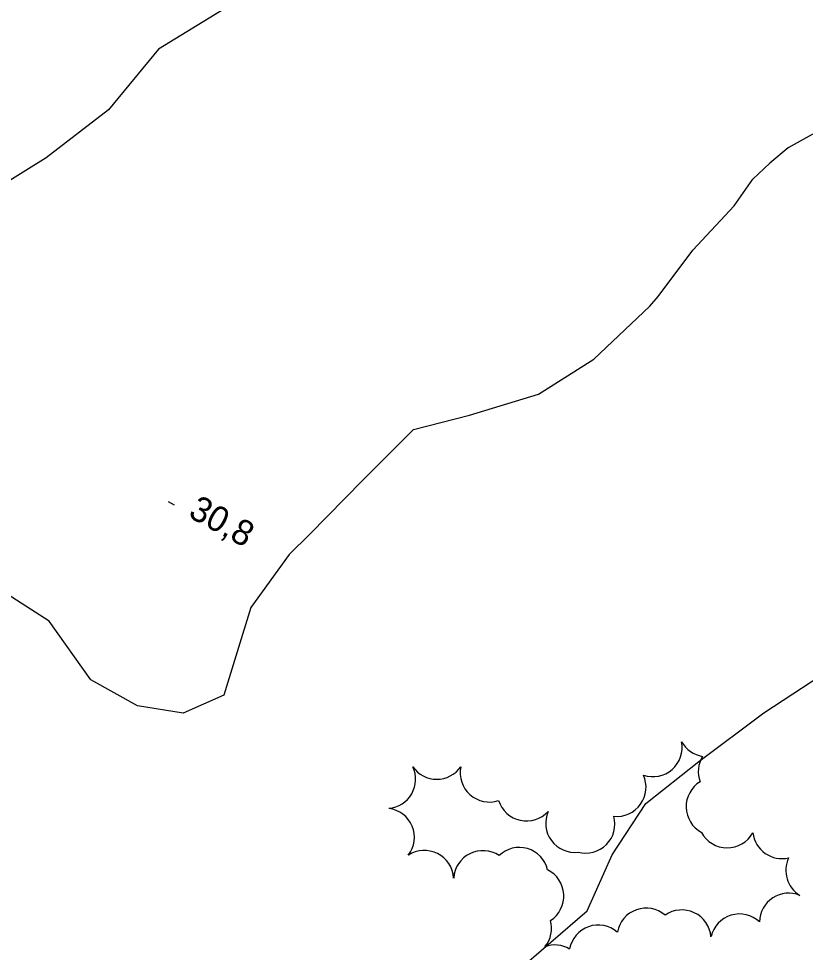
# Model space of a CAD drawing. Extents: x 219136 to 222520, y 5421589 to 5424530.
# Drawn here: x 219665.7 to 219758.8, y 5423413.3 to 5423523.8 of the extents above; entities that cross this region are included whole.
import ezdxf

# ---------------------------------------------------------------- set-up
doc = ezdxf.new("R2010")
doc.units = 0
for name, color, linetype in [('Level 22', 7, 'Continuous'), ('Level 3', 7, 'Continuous'), ('Level 44', 7, 'Continuous')]:
    doc.layers.add(name, color=color, linetype=linetype)

msp = doc.modelspace()

# ---------------------------------------------------------------- linework, layer by layer
at = {"layer": 'Level 22'}
for points in [[(219707.67, 5423397.88), (219714.95, 5423402.49), (219724.41, 5423410.75), (219733, 5423418.18), (219735.96, 5423424.81), (219739.97, 5423430.9), (219746.23, 5423435.87), (219753.94, 5423441.61), (219762.96, 5423447.53), (219776.39, 5423460.4), (219785.92, 5423468.85), (219798.8, 5423476.25), (219806.46, 5423483.03), (219814.25, 5423489.43), (219822.48, 5423494.55), (219828.76, 5423500.55), (219835.56, 5423505.18), (219844.92, 5423509.69), (219856.08, 5423514), (219863.03, 5423517.94), (219871.64, 5423523.39), (219878.98, 5423527.21)], [(219690.2, 5423525.01), (219682.26, 5423520.16), (219676.33, 5423512.97), (219668.95, 5423507.27), (219663.18, 5423503.68)], [(219799.26, 5423476.66), (219796.99, 5423482.79), (219794.42, 5423489.19), (219791.77, 5423494.71), (219785.87, 5423501.43), (219781.88, 5423505.88), (219777.63, 5423511.69), (219775.45, 5423513.65), (219769.59, 5423512.52), (219765.85, 5423511.73), (219759.64, 5423510.05), (219756.81, 5423508.45), (219754.65, 5423506.65), (219752.64, 5423504.78)], [(219741.4, 5423490.87), (219745.54, 5423496.34), (219750.43, 5423501.62), (219752.64, 5423504.78)], [(219700.19, 5423462.75), (219706.41, 5423469.1), (219712.47, 5423475.12), (219719.09, 5423476.84), (219727.24, 5423479.3), (219733.82, 5423483.46), (219740.45, 5423489.74), (219741.4, 5423490.87)], [(219700.19, 5423462.75), (219697.74, 5423460.35), (219693.18, 5423454.06), (219691.58, 5423448.82), (219690, 5423443.72), (219685.18, 5423441.58), (219679.79, 5423442.43), (219674.25, 5423445.5), (219669.32, 5423452.45), (219662.09, 5423457.07)]]:
    msp.add_lwpolyline(points, dxfattribs=at)
at = {"layer": 'Level 3'}
msp.add_line((219683.41, 5423466.6), (219684.11, 5423466.22), dxfattribs=at)
at = {"layer": 'Level 44'}
for centre, start, end in [((219740.8, 5423437.52), 251.1529, 11.1529), ((219747.22, 5423439.87), 209.103, 260.566), ((219749.63, 5423434.67), 149.103, 200.566), ((219709.24, 5423433.76), 275.0101, 24.911), ((219715.21, 5423437.21), 215.0101, 324.911), ((219721.44, 5423434.51), 168.3005, 288.3005), ((219736.52, 5423432.81), 264.3113, 24.3113), ((219748.19, 5423430.51), 121.54, 241.54), ((219725.83, 5423432.27), 197.6581, 317.6581), ((219709.09, 5423426.87), 322.6016, 82.6016), ((219731.56, 5423428.55), 156.3535, 276.3535), ((219732.83, 5423428.46), 255.1809, 15.1809), ((219749.6, 5423429.09), 207.9947, 330.7644), ((219756.06, 5423427.82), 187.0047, 283.1006), ((219713.74, 5423421.87), 3.1708, 123.1708), ((219720.66, 5423421.84), 56.3432, 176.3432), ((219724.97, 5423422.22), 13.7019, 133.7019), ((219759.99, 5423422.97), 154.8931, 238.7597), ((219726.78, 5423419.94), 303.3221, 63.3221), ((219756.87, 5423416.81), 67.6835, 178.7597), ((219739.99, 5423415.04), 49.4877, 169.4877), ((219744.22, 5423414.83), 4.8137, 124.8137), ((219751.05, 5423414.35), 47.0477, 167.0477), ((219725.34, 5423416.14), 320.5716, 15.2164), ((219734.34, 5423413.04), 49.5928, 169.5928), ((219729.18, 5423410.68), 59.5003, 109.608)]:
    msp.add_arc(centre, 3.46, start, end, dxfattribs=at)

# ---------------------------------------------------------------- texts
at = {"layer": 'Level 3'}
msp.add_text('30,8', height=3, rotation=331.383, dxfattribs=at).set_placement((219685.65, 5423464.86))

doc.saveas('drawing.dxf')
